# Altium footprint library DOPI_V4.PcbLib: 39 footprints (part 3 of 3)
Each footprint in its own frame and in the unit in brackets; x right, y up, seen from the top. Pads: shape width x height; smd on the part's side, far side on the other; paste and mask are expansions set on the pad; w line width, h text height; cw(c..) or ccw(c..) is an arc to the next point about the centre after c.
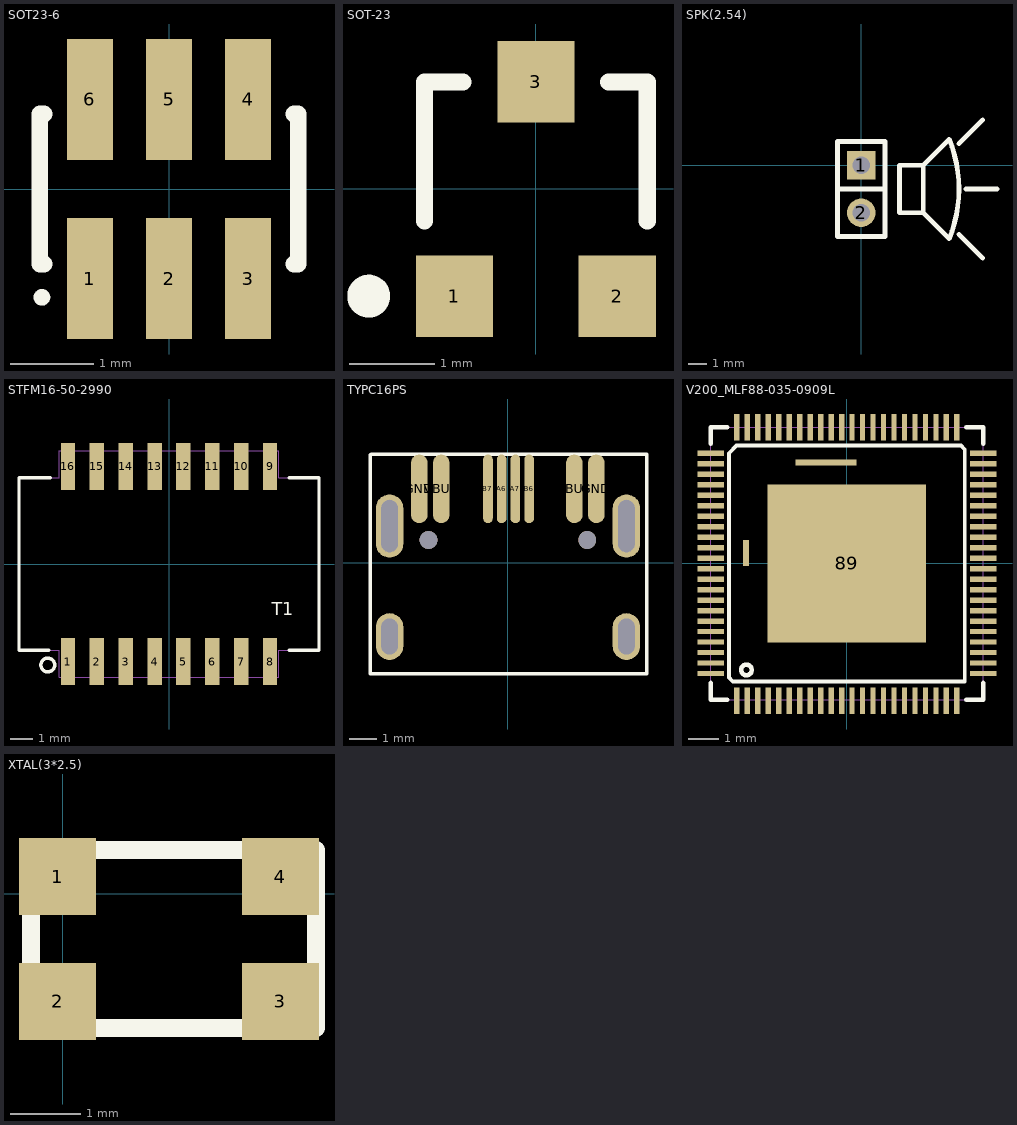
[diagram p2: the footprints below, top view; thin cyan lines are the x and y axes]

## SOT23-6 [mm] "SOT-23/SC-74A; 5 Leads; Body 3.1 x 3 mm, inc. leads (LxW max)"
height 1.45
pads (6):
  rect 0.55x1.45 smd: 1(-0.95,-1.075) 2(0,-1.075) 3(0.95,-1.075) 4(0.95,1.075) 5(0,1.075) 6(-0.95,1.075)
Top Overlay:
  circle w0.1: c-1.525,-1.3 r0.05
  lines w0.2: -1.5,-0.9 -1.55,-0.9 -1.55,0.9 -1.5,0.9 ; 1.5,-0.9 1.55,-0.9 1.55,0.9 1.5,0.9

## SOT-23 [mm] "SOT-23; 3 Leads; Body 3.0 x 2.6 mm, inc. leads (LxW max)"
height 1.1
pads (3):
  rect 0.9x0.95 smd: 1(-0.95,-1.25) 2(0.95,-1.25) 3(0,1.25)
Top Overlay:
  circle w0.25: c-1.95,-1.25 r0.125
  lines w0.2: -1.3,-0.375 -1.3,1.25 -0.85,1.25 ; 0.85,1.25 1.3,1.25 1.3,-0.375

## SPK(2.54) [mil]
pads (2):
  rect 60x60 hole 36: 1(0,0)
  round 60 hole 36: 2(0,-100)
Top Overlay:
  lines w10: -50,-50 50,-50 ; 184.33,-154.72 ccw(c-70,-50) 184.33,54.72 ; 184.33,-154.33 130,-100 ; 184.33,54.33 130,0 ; 205,-145 255,-195 ; 205,45 255,95 ; 220,-50 285,-50 ; 130,-100 80,-100 80,0 130,0 ; 130,-100 130,0 ; -50,-150 -50,50 50,50 50,-150 -50,-150

## STFM16-50-2990 [mil]
pads (16):
  rect 25x82 smd: 1(-175,-169) 2(-125,-169) 3(-75,-169) 4(-25,-169) 5(25,-169) 6(75,-169) 7(125,-169) 8(175,-169) 9(175,169) 10(125,169) 11(75,169) 12(25,169) 13(-25,169) 14(-75,169) 15(-125,169) 16(-175,169)
Top Overlay:
  circle w6: c-209.92,-174.96 r12
  lines w6: -208,-149.61 -259.84,-149.61 -259.84,149.61 -205.34,149.61 ; 208,-149.61 259.84,-149.61 259.84,149.61 208,149.61
  text "T1" at 178,-89 h22
Mechanical 16:
  lines w1: -259.84,-149.61 -259.84,149.61 -190,149.61 -190,195.87 190,195.87 190,149.61 259.84,149.61 259.84,-149.61 190,-149.61 190,-195.87 -190,-195.87 -190,-149.61 -259.84,-149.61

## TYPC16PS [mm]
pads (14):
  oval 0.35x2.5 smd: A6(-0.23,2.69) A7(0.27,2.69) B6(0.77,2.69) B7(-0.73,2.69)
  oval 0.6x2.5 smd: GND(-3.23,2.69) GND(3.22,2.69) VBUS(-2.43,2.69) VBUS(2.42,2.69)
  oval 1x1.7 hole 0.6 slot 1.3 at 90 deg: ""(-4.314,-2.69) ""(4.315,-2.69)
  oval 1x2.3 hole 0.6 slot 1.9 at 90 deg: ""(-4.314,1.336) ""(4.315,1.336)
  round 0.65 hole 0.65: ""(-2.895,0.828) ""(2.885,0.828)
Top Overlay:
  lines w0.127: -5.013,3.166 -5.013,-4.047 5.047,-4.047 5.047,3.954 ; -5.011,3.039 -5.011,3.928 -4.986,3.954 ; -4.96,3.954 5.022,3.954

## V200_MLF88-035-0909L [mil]
pads (91):
  rect 7x35 smd: 1(-144.69,-180.42) 2(-130.91,-180.42) 3(-117.13,-180.42) 4(-103.35,-180.42) 5(-89.57,-180.42) 6(-75.79,-180.42) 7(-62.01,-180.42) 8(-48.23,-180.42) 9(-34.45,-180.42) 10(-20.67,-180.42) 11(-6.89,-180.42) 12(6.89,-180.42) 13(20.67,-180.42) 14(34.45,-180.42) 15(48.23,-180.42) 16(62.01,-180.42) 17(75.79,-180.42) 18(89.57,-180.42) 19(103.35,-180.42) 20(117.13,-180.42) 21(130.91,-180.42) 22(144.69,-180.42) 45(144.69,179) 46(130.91,179) 47(117.13,179) 48(103.35,179) 49(89.57,179) 50(75.79,179) 51(62.01,179) 52(48.23,179) 53(34.45,179) 54(20.67,179) 55(6.89,179) 56(-6.89,179) 57(-20.67,179) 58(-34.45,179) 59(-48.23,179) 60(-62.01,179) 61(-75.79,179) 62(-89.57,179) 63(-103.35,179) 64(-117.13,179) 65(-130.91,179) 66(-144.69,179)
  rect 35x7 smd: 23(179.42,-144.69) 24(179.42,-130.91) 25(179.42,-117.13) 26(179.42,-103.35) 27(179.42,-89.57) 28(179.42,-75.79) 29(179.42,-62.01) 30(179.42,-48.23) 31(179.42,-34.45) 32(179.42,-20.67) 33(179.42,-6.89) 34(179.42,6.89) 35(179.42,20.67) 36(179.42,34.45) 37(179.42,48.23) 38(179.42,62.01) 39(179.42,75.79) 40(179.42,89.57) 41(179.42,103.35) 42(179.42,117.13) 43(179.42,130.91) 44(179.42,144.69) 67(-179,144.69) 68(-179,130.91) 69(-179,117.13) 70(-179,103.35) 71(-179,89.57) 72(-179,75.79) 73(-179,62.01) 74(-179,48.23) 75(-179,34.45) 76(-179,20.67) 77(-179,6.89) 78(-179,-6.89) 79(-179,-20.67) 80(-179,-34.45) 81(-179,-48.23) 82(-179,-62.01) 83(-179,-75.79) 84(-179,-89.57) 85(-179,-103.35) 86(-179,-117.13) 87(-179,-130.91) 88(-179,-144.69)
  rect 208x208 smd: 89(0,0)
  rect 80x8 smd: 90(-27.56,132.48)
  rect 8x34 smd: 91(-132.48,13.78)
Top Overlay:
  circle w6: c-132,-140 r7
  lines w5: -155,-150 -150,-155 155,-155 155,150 150,155 -145,155 -155,145 -155,-150
  lines w6: -179.13,-157.19 -179.13,-179.13 -157.19,-179.13 ; -179.13,157.19 -179.13,179.13 -157.19,179.13 ; 157.19,-179.13 179.13,-179.13 179.13,-157.19 ; 157.19,179.13 179.13,179.13 179.13,157.19
Mechanical 16:
  lines w1: -179.13,-179.13 179.13,-179.13 179.13,179.13 -179.13,179.13 -179.13,-179.13

## XTAL(3*2.5) [mm]
pads (4):
  rect 1.1x1.1 smd: 1(-0.076,0.241) 2(-0.076,-1.537) 4(3.099,0.241)
  rect 1.1x1.1 smd paste+0: 3(3.099,-1.537)
Top Overlay:
  lines w0.254: -0.457,-1.918 -0.457,0.622 3.607,0.622 3.607,-1.918 -0.457,-1.918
